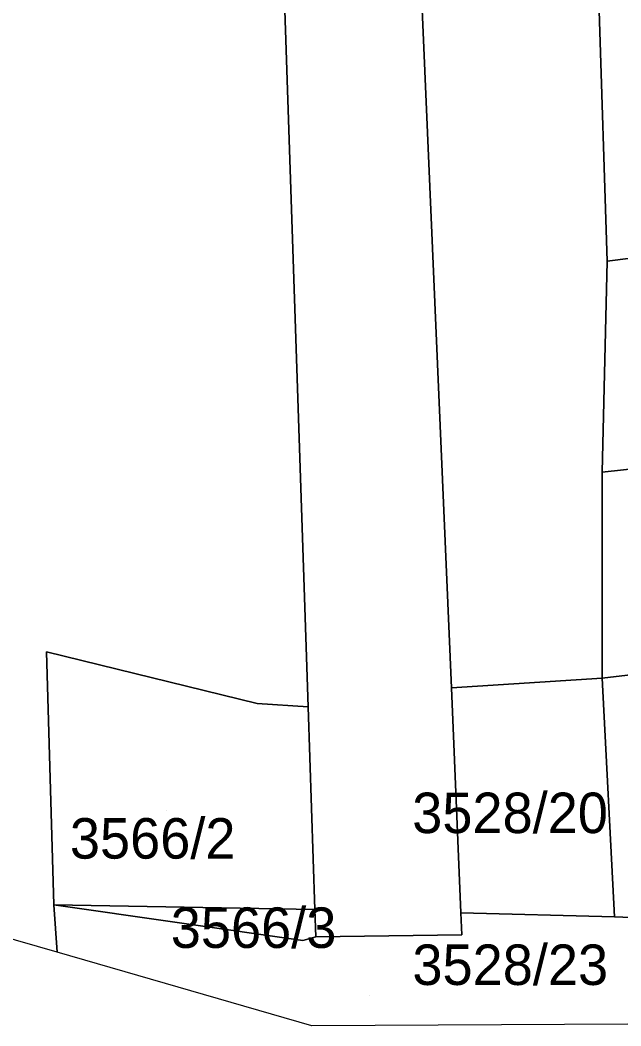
# Model space of a CAD drawing. Extents: x -262657 to -261595, y -1238015 to -1237156.
# Drawn here: x -262353.88 to -262324.21, y -1237552.13 to -1237502.46 of the extents above; entities that cross this region are included whole.
import ezdxf

# ---------------------------------------------------------------- set-up
doc = ezdxf.new("R2010")
doc.units = 0
for name, color, linetype in [('body_kn', 7, 'Continuous'), ('kladpar_druhypozemkov', 7, 'Continuous'), ('kladpar_hranice', 7, 'Continuous'), ('kladpar_parcelnecisla', 7, 'Continuous'), ('kladpar_plochy', 7, 'Continuous')]:
    doc.layers.add(name, color=color, linetype=linetype)

msp = doc.modelspace()

# ---------------------------------------------------------------- linework, layer by layer
at = {"layer": 'body_kn'}
for p, q in [((-262324.89, -1237514.36), (-262324.89, -1237514.36)), ((-262325.13, -1237524.79), (-262325.13, -1237524.79)), ((-262352.58, -1237533.65), (-262352.58, -1237533.65)), ((-262325.13, -1237534.95), (-262325.13, -1237534.95)), ((-262325.13, -1237534.95), (-262325.13, -1237534.95)), ((-262332.58, -1237535.43), (-262332.58, -1237535.43)), ((-262342.18, -1237536.21), (-262342.18, -1237536.21)), ((-262339.66, -1237536.38), (-262339.66, -1237536.38)), ((-262352.22, -1237546.15), (-262352.22, -1237546.15)), ((-262352.22, -1237546.15), (-262352.22, -1237546.15)), ((-262339.33, -1237546.39), (-262339.33, -1237546.39)), ((-262332.11, -1237546.54), (-262332.11, -1237546.54)), ((-262332.11, -1237546.54), (-262332.11, -1237546.54)), ((-262324.52, -1237546.74), (-262324.52, -1237546.74)), ((-262324.52, -1237546.74), (-262324.52, -1237546.74)), ((-262339.92, -1237547.91), (-262339.92, -1237547.91)), ((-262339.28, -1237547.74), (-262339.28, -1237547.74)), ((-262332.06, -1237547.64), (-262332.06, -1237547.64)), ((-262352.05, -1237548.49), (-262352.05, -1237548.49)), ((-262339.48, -1237552.13), (-262339.48, -1237552.13))]:
    msp.add_line(p, q, dxfattribs=at)
at = {"layer": 'kladpar_druhypozemkov'}
for p, q in [((-262328.08, -1237541.15), (-262328.08, -1237541.15)), ((-262346.65, -1237541.48), (-262346.65, -1237541.48)), ((-262343.1, -1237546.94), (-262343.1, -1237546.94)), ((-262336.63, -1237550.61), (-262336.63, -1237550.61))]:
    msp.add_line(p, q, dxfattribs=at)
at = {"layer": 'kladpar_hranice'}
for p, q in [((-262325.13, -1237534.95), (-262324.52, -1237546.74)), ((-262324.52, -1237546.74), (-262332.11, -1237546.54)), ((-262332.11, -1237546.54), (-262324.52, -1237546.74))]:
    msp.add_line(p, q, dxfattribs=at)
for points in [[(-262326.86, -1237377.31), (-262329, -1237395.2), (-262330, -1237408.65), (-262330.77, -1237419.19), (-262331.73, -1237432.47), (-262332.03, -1237436.68), (-262333.57, -1237463.66), (-262334.8, -1237485.25), (-262334.58, -1237488.96), (-262332.58, -1237535.43), (-262332.11, -1237546.54), (-262332.06, -1237547.64), (-262339.28, -1237547.74), (-262339.33, -1237546.39), (-262339.66, -1237536.38), (-262341.34, -1237486.23), (-262339.94, -1237457.24), (-262338.79, -1237433.17), (-262338.68, -1237430.7), (-262338.44, -1237425.28), (-262337.84, -1237412.47), (-262336.73, -1237391.76)], [(-262331.73, -1237432.47), (-262327.33, -1237433.68), (-262326.82, -1237443.01), (-262326.27, -1237469.57), (-262326.03, -1237481.62), (-262325.93, -1237482.92), (-262325.3, -1237501.49), (-262324.89, -1237514.36), (-262325.13, -1237524.79), (-262325.13, -1237534.95), (-262332.58, -1237535.43), (-262334.58, -1237488.96), (-262334.8, -1237485.25), (-262333.57, -1237463.66), (-262332.03, -1237436.68), (-262331.73, -1237432.47)], [(-262341.34, -1237486.23), (-262339.66, -1237536.38), (-262342.18, -1237536.21), (-262352.58, -1237533.65), (-262352.22, -1237546.15), (-262352.05, -1237548.49), (-262357.15, -1237547.02), (-262357.06, -1237545.45), (-262358.56, -1237545.46), (-262358.56, -1237543.97), (-262359.1, -1237543.98), (-262359.09, -1237544.7), (-262361.13, -1237544.74), (-262369.08, -1237544.9), (-262375.44, -1237545.04), (-262377.62, -1237545.08), (-262377.68, -1237544.19), (-262378.47, -1237544.21), (-262378.45, -1237545.51), (-262380.63, -1237545.53), (-262388.95, -1237537.5), (-262394.66, -1237531.99), (-262395.88, -1237531.76), (-262406.23, -1237521.95)], [(-262302.16, -1237497.96), (-262297.12, -1237496.83), (-262296.18, -1237497.18), (-262294.34, -1237510.76), (-262310.72, -1237512.59), (-262317.09, -1237513.38), (-262324.89, -1237514.36), (-262325.3, -1237501.49), (-262302.16, -1237497.96)], [(-262317.09, -1237513.38), (-262313.45, -1237520), (-262307.55, -1237517.4), (-262310.72, -1237512.59), (-262294.34, -1237510.76), (-262292.96, -1237521.27), (-262325.13, -1237524.79), (-262324.89, -1237514.36), (-262317.09, -1237513.38)], [(-262325.13, -1237534.95), (-262325.13, -1237524.79), (-262292.96, -1237521.27), (-262289.96, -1237520.85), (-262289.49, -1237526.04), (-262283.11, -1237525.44), (-262282.8, -1237530.05), (-262289.03, -1237530.71), (-262316.09, -1237533.89), (-262325.13, -1237534.95)], [(-262352.22, -1237546.15), (-262352.58, -1237533.65), (-262342.18, -1237536.21), (-262339.66, -1237536.38), (-262339.33, -1237546.39), (-262352.22, -1237546.15)], [(-262316.09, -1237533.89), (-262314.73, -1237535.59), (-262313.49, -1237537.02), (-262312.39, -1237538.16), (-262310.67, -1237539.95), (-262308.79, -1237541.77), (-262306.38, -1237544.06), (-262305.26, -1237545.09), (-262302.19, -1237547.65), (-262309.76, -1237547.34), (-262311.39, -1237547.27), (-262315.22, -1237547.11), (-262316.43, -1237547.07), (-262324.52, -1237546.74), (-262325.13, -1237534.95), (-262316.09, -1237533.89)], [(-262332.11, -1237546.54), (-262332.58, -1237535.43), (-262325.13, -1237534.95)], [(-262352.22, -1237546.15), (-262339.33, -1237546.39), (-262339.28, -1237547.74), (-262339.92, -1237547.91), (-262352.22, -1237546.15)], [(-262352.22, -1237546.15), (-262339.92, -1237547.91), (-262339.28, -1237547.74), (-262332.06, -1237547.64), (-262332.11, -1237546.54)], [(-262324.52, -1237546.74), (-262316.43, -1237547.07), (-262315.18, -1237549.37), (-262315.35, -1237550.39), (-262316.14, -1237551.27), (-262317.1, -1237551.5), (-262317.63, -1237552.02), (-262339.48, -1237552.13), (-262352.05, -1237548.49), (-262352.22, -1237546.15)]]:
    msp.add_lwpolyline(points, dxfattribs=at)
at = {"layer": 'kladpar_plochy'}
for points in [[(-262326.86, -1237377.31), (-262329, -1237395.2), (-262330, -1237408.65), (-262330.77, -1237419.19), (-262331.73, -1237432.47), (-262332.03, -1237436.68), (-262333.57, -1237463.66), (-262334.8, -1237485.25), (-262334.58, -1237488.96), (-262332.58, -1237535.43), (-262332.11, -1237546.54), (-262332.06, -1237547.64), (-262339.28, -1237547.74), (-262339.33, -1237546.39), (-262339.66, -1237536.38), (-262341.34, -1237486.23), (-262339.94, -1237457.24), (-262338.79, -1237433.17), (-262338.68, -1237430.7), (-262338.44, -1237425.28), (-262337.84, -1237412.47), (-262336.73, -1237391.76)], [(-262341.34, -1237486.23), (-262339.66, -1237536.38), (-262342.18, -1237536.21), (-262352.58, -1237533.65), (-262352.22, -1237546.15), (-262352.05, -1237548.49), (-262357.15, -1237547.02), (-262357.06, -1237545.45), (-262358.56, -1237545.46), (-262358.56, -1237543.97), (-262359.1, -1237543.98), (-262359.09, -1237544.7), (-262361.13, -1237544.74), (-262369.08, -1237544.9), (-262375.44, -1237545.04), (-262377.62, -1237545.08), (-262377.68, -1237544.19), (-262378.47, -1237544.21), (-262378.45, -1237545.51), (-262380.63, -1237545.53), (-262388.95, -1237537.5), (-262394.66, -1237531.99), (-262395.88, -1237531.76), (-262406.23, -1237521.95)]]:
    msp.add_lwpolyline(points, dxfattribs=at)
for points in [[(-262331.73, -1237432.47), (-262327.33, -1237433.68), (-262326.82, -1237443.01), (-262326.27, -1237469.57), (-262326.03, -1237481.62), (-262325.93, -1237482.92), (-262325.3, -1237501.49), (-262324.89, -1237514.36), (-262325.13, -1237524.79), (-262325.13, -1237534.95), (-262332.58, -1237535.43), (-262334.58, -1237488.96), (-262334.8, -1237485.25), (-262333.57, -1237463.66), (-262332.03, -1237436.68)], [(-262302.16, -1237497.96), (-262297.12, -1237496.83), (-262296.18, -1237497.18), (-262294.34, -1237510.76), (-262310.72, -1237512.59), (-262317.09, -1237513.38), (-262324.89, -1237514.36), (-262325.3, -1237501.49)], [(-262317.09, -1237513.38), (-262313.45, -1237520), (-262307.55, -1237517.4), (-262310.72, -1237512.59), (-262294.34, -1237510.76), (-262292.96, -1237521.27), (-262325.13, -1237524.79), (-262324.89, -1237514.36)], [(-262325.13, -1237534.95), (-262325.13, -1237524.79), (-262292.96, -1237521.27), (-262289.96, -1237520.85), (-262289.49, -1237526.04), (-262283.11, -1237525.44), (-262282.8, -1237530.05), (-262289.03, -1237530.71), (-262316.09, -1237533.89)], [(-262352.22, -1237546.15), (-262352.58, -1237533.65), (-262342.18, -1237536.21), (-262339.66, -1237536.38), (-262339.33, -1237546.39)], [(-262316.09, -1237533.89), (-262314.73, -1237535.59), (-262313.49, -1237537.02), (-262312.39, -1237538.16), (-262310.67, -1237539.95), (-262308.79, -1237541.77), (-262306.38, -1237544.06), (-262305.26, -1237545.09), (-262302.19, -1237547.65), (-262309.76, -1237547.34), (-262311.39, -1237547.27), (-262315.22, -1237547.11), (-262316.43, -1237547.07), (-262324.52, -1237546.74), (-262325.13, -1237534.95)], [(-262325.13, -1237534.95), (-262324.52, -1237546.74), (-262332.11, -1237546.54), (-262332.58, -1237535.43)], [(-262352.22, -1237546.15), (-262339.33, -1237546.39), (-262339.28, -1237547.74), (-262339.92, -1237547.91)], [(-262352.22, -1237546.15), (-262339.92, -1237547.91), (-262339.28, -1237547.74), (-262332.06, -1237547.64), (-262332.11, -1237546.54), (-262324.52, -1237546.74), (-262316.43, -1237547.07), (-262315.18, -1237549.37), (-262315.35, -1237550.39), (-262316.14, -1237551.27), (-262317.1, -1237551.5), (-262317.63, -1237552.02), (-262339.48, -1237552.13), (-262352.05, -1237548.49)]]:
    msp.add_lwpolyline(points, close=True, dxfattribs=at)

# ---------------------------------------------------------------- texts
at = {"layer": 'kladpar_parcelnecisla'}
for s, p in [('3528/20', (-262334.515, -1237542.61)), ('3566/2', (-262351.424, -1237543.87)), ('3566/3', (-262346.44, -1237548.28)), ('3528/23', (-262334.506, -1237550.11))]:
    msp.add_text(s, height=2, dxfattribs=at).set_placement(p)

doc.saveas('drawing.dxf')
